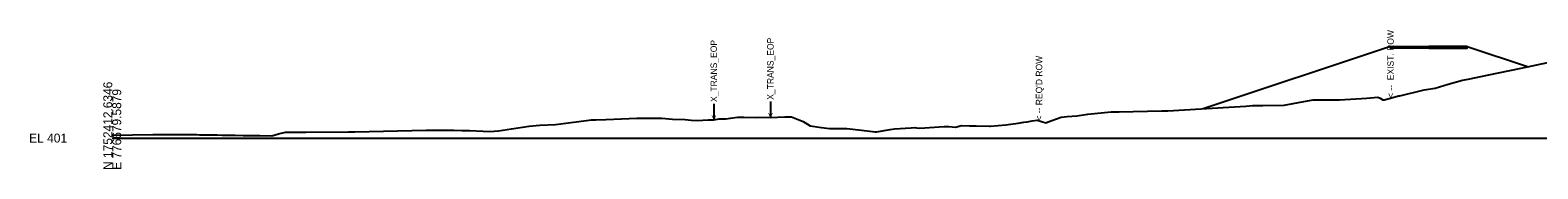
# Model space of a CAD drawing. Extents: x 776426 to 854588, y 1736205 to 1756790.
# Drawn here: x 805845.1 to 806316.9, y 1753205.1 to 1753248.6 of the extents above; entities that cross this region are included whole.
import ezdxf

# ---------------------------------------------------------------- set-up
doc = ezdxf.new("R2010")
doc.units = 0
for name, color, linetype in [('DTM CONTOURS_MAJOR_TX', 7, 'Continuous'), ('DTM_X_FLOW_ARROWS', 7, 'Continuous'), ('X_TRANS_EOP', 7, 'Continuous'), ('XS_P_DR_GRAVEL', 7, 'Continuous'), ('XS_P_GROUND', 7, 'Continuous'), ('XS_P_ROW', 7, 'Continuous'), ('XS_X_PAVEMENT', 7, 'Continuous'), ('XS_X_ROW', 7, 'Continuous')]:
    doc.layers.add(name, color=color, linetype=linetype)

msp = doc.modelspace()

# ---------------------------------------------------------------- linework, layer by layer
at = {"layer": 'DTM CONTOURS_MAJOR_TX'}
msp.add_line((805870.79, 1753214.76), (806370.79, 1753214.76), dxfattribs=at)
at = {"layer": 'DTM_X_FLOW_ARROWS'}
msp.add_lwpolyline([(805870.79, 1753215.63), (805883.52, 1753215.88), (805886.39, 1753215.87), (805891.09, 1753215.89), (805892.75, 1753215.88), (805893.62, 1753215.86), (805897.29, 1753215.84), (805898.05, 1753215.81), (805901.32, 1753215.8), (805902.43, 1753215.76), (805903.67, 1753215.72), (805905.21, 1753215.68), (805907.43, 1753215.63), (805909.26, 1753215.62), (805911.8, 1753215.55), (805912.19, 1753215.54), (805915.21, 1753215.56), (805916.96, 1753215.58), (805920.77, 1753215.47), (805922.78, 1753216.04), (805925, 1753216.59), (805931.37, 1753216.63), (805944.72, 1753216.74), (805946.71, 1753216.76), (805968.97, 1753217.27), (805977.68, 1753217.22), (805980.16, 1753217.17), (805981.41, 1753217.15), (805981.75, 1753217.14), (805982.57, 1753217.1), (805986.81, 1753216.91), (805988.89, 1753216.83), (805991.67, 1753217.04), (805995.69, 1753217.67), (806001.29, 1753218.44), (806004.62, 1753218.79), (806009.5, 1753219), (806010.32, 1753219.08), (806020.78, 1753220.47), (806022.07, 1753220.47), (806025.24, 1753220.61), (806030.16, 1753220.79), (806034.92, 1753221), (806037.74, 1753221.01), (806042.8, 1753220.95), (806046.1, 1753220.72), (806050.03, 1753220.6), (806051.95, 1753220.35), (806053.92, 1753220.24), (806057.31, 1753220.47), (806058.99, 1753220.5), (806060.75, 1753220.74), (806062.82, 1753220.81), (806064.22, 1753221), (806066.47, 1753221.27), (806067.77, 1753221.34), (806068.4, 1753221.34), (806072.05, 1753221.25), (806073.07, 1753221.28), (806076.72, 1753221.21), (806081.27, 1753221.43), (806083.35, 1753221.45), (806087.01, 1753219.95), (806089.19, 1753218.63), (806092.73, 1753218.09), (806095.19, 1753217.79), (806100.68, 1753217.76), (806101.61, 1753217.65), (806106.99, 1753217.03), (806109.56, 1753216.7), (806109.95, 1753216.75), (806114.2, 1753217.47), (806115.58, 1753217.61), (806120.78, 1753217.95), (806121.88, 1753218.02), (806122.5, 1753217.93), (806123.48, 1753217.9), (806131.16, 1753218.35), (806132.01, 1753218.4), (806132.52, 1753218.41), (806134.62, 1753218.21), (806136.5, 1753218.65), (806139.04, 1753218.6), (806141.1, 1753218.56), (806145.28, 1753218.47), (806145.65, 1753218.5), (806150.45, 1753218.87), (806154.23, 1753219.44), (806156.06, 1753219.78), (806157.11, 1753219.9), (806158.64, 1753220.15), (806160.22, 1753220.4), (806162.95, 1753219.57), (806163.7, 1753219.86), (806167.76, 1753221.31), (806169.56, 1753221.51), (806172.6, 1753221.75), (806176.08, 1753222.23), (806182.3, 1753222.84), (806183.4, 1753222.94), (806184.37, 1753222.97), (806185.85, 1753222.99), (806199.15, 1753223.35), (806201.06, 1753223.35), (806220.2, 1753224.43), (806225.53, 1753224.76), (806227.54, 1753224.93), (806230.79, 1753225.01), (806237.55, 1753225.11), (806244.84, 1753226.42), (806246.6, 1753226.72), (806247.06, 1753226.78), (806252.2, 1753226.78), (806254.28, 1753226.76), (806254.83, 1753226.76), (806263.41, 1753227.31), (806266.83, 1753227.6), (806267.51, 1753227.29), (806268.37, 1753226.78), (806268.76, 1753226.78), (806270.74, 1753227.32), (806271.09, 1753227.43), (806271.47, 1753227.53), (806273.25, 1753227.97), (806273.67, 1753228.06), (806281.33, 1753229.86), (806284.75, 1753230.46), (806288.83, 1753231.69), (806293.31, 1753232.88), (806295.13, 1753233.29), (806299.52, 1753234.2), (806301, 1753234.5), (806311.69, 1753236.65), (806319.99, 1753238.43)], dxfattribs=at)
at = {"layer": 'X_TRANS_EOP'}
for p, q in [((806059, 1753225.5), (806059, 1753220.5)), ((806076.72, 1753226.21), (806076.72, 1753221.21))]:
    msp.add_line(p, q, dxfattribs=at)
at = {"layer": 'XS_P_DR_GRAVEL'}
for points in [[(806282.79, 1753243.52), (806282.79, 1753243.02), (806270.79, 1753243.02), (806270.79, 1753243.52), (806282.79, 1753243.52)], [(806282.79, 1753243.52), (806282.79, 1753243.02), (806294.79, 1753243.02), (806294.79, 1753243.52), (806282.79, 1753243.52)]]:
    msp.add_lwpolyline(points, dxfattribs=at)
at = {"layer": 'XS_P_GROUND'}
for points in [[(806270.79, 1753243.52), (806212.16, 1753223.98)], [(806294.79, 1753243.52), (806313.96, 1753237.13)]]:
    msp.add_lwpolyline(points, dxfattribs=at)

# ---------------------------------------------------------------- texts
at = {"layer": 'DTM CONTOURS_MAJOR_TX'}
for s, p in [('N 1752412.6346', (805870.79, 1753204.76)), ('E 776679.5879', (805873.59, 1753204.76))]:
    msp.add_text(s, height=2.8, rotation=90, dxfattribs=at).set_placement(p)
msp.add_text('EL 401', height=2.8, dxfattribs=at).set_placement((805844.79, 1753213.36))
at = {"layer": 'XS_P_ROW'}
msp.add_text("< -- REQ'D ROW", height=2, rotation=90, dxfattribs=at).set_placement((806161.79, 1753220.23))
at = {"layer": 'XS_X_PAVEMENT'}
for p in [(806060, 1753220.5), (806077.72, 1753221.21)]:
    msp.add_text('< --  X_TRANS_EOP', height=2, rotation=90, dxfattribs=at).set_placement(p)
at = {"layer": 'XS_X_ROW'}
msp.add_text('< --  EXIST. ROW', height=2, rotation=90, dxfattribs=at).set_placement((806271.79, 1753227.34))

doc.saveas('drawing.dxf')
